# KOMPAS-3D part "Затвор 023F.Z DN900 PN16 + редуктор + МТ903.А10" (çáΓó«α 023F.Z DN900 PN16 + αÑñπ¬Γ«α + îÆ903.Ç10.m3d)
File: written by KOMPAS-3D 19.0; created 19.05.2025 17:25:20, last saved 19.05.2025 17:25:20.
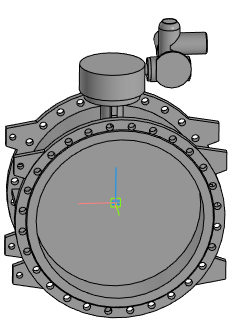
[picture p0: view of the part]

Document properties: Полное имя файла: Затвор 023F.Z DN900 PN16 + редуктор + МТ903.А10.a3d

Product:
- Part/product: Затвор 023F.Z DN900 PN16 + редуктор + МТ903.А10
    Масса: 1137

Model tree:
1. Операция без истории:1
